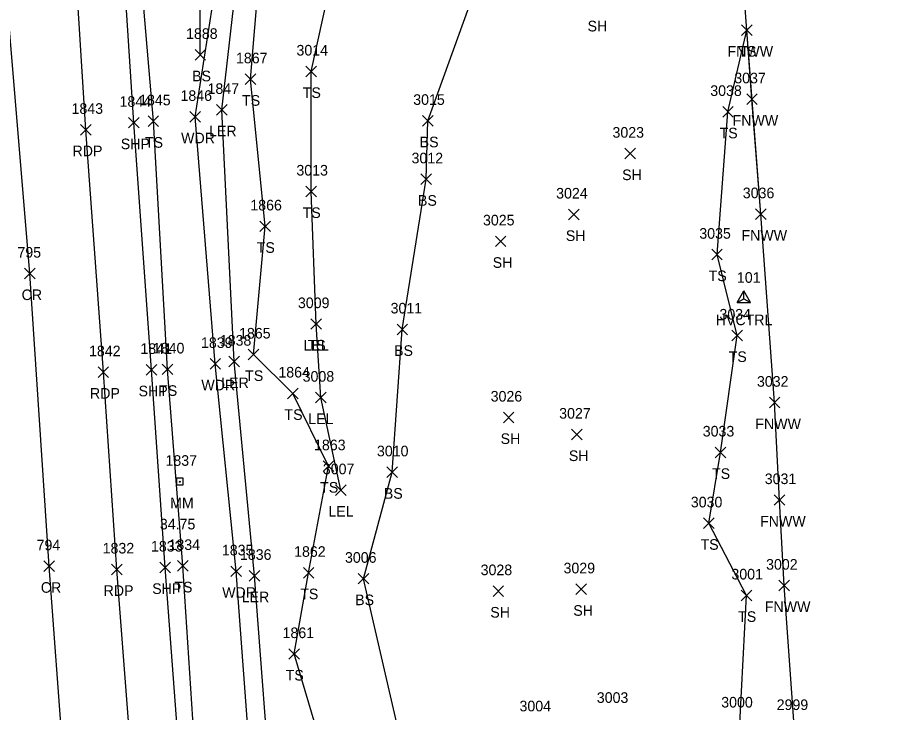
# Model space of a CAD drawing. Extents: x 1650221 to 1650634, y 244606 to 249996.
# Drawn here: x 1650455.2 to 1650620.5, y 244867.1 to 244998.2 of the extents above; entities that cross this region are included whole.
import ezdxf

# ---------------------------------------------------------------- set-up
doc = ezdxf.new("R2010")
doc.units = 0
for name, color, linetype in [('C_A', 7, 'Continuous'), ('C_I', 7, 'Continuous'), ('CPSM', 7, 'Continuous'), ('L_A', 7, 'Continuous'), ('L_I', 7, 'Continuous'), ('L_TIC', 7, 'Continuous'), ('LARO', 7, 'Continuous'), ('LAWA', 7, 'Continuous'), ('LELB', 7, 'Continuous'), ('LFNC', 7, 'Continuous'), ('LSOGP', 7, 'Continuous'), ('P_A', 7, 'Continuous'), ('P_I', 7, 'Continuous'), ('P_TIC', 7, 'Continuous'), ('PET', 7, 'Continuous'), ('PRC', 7, 'Continuous'), ('PSP', 7, 'Continuous'), ('S_A', 7, 'Continuous'), ('S_C', 7, 'Continuous'), ('S_I', 7, 'Continuous'), ('SRM', 7, 'Continuous')]:
    doc.layers.add(name, color=color, linetype=linetype)

msp = doc.modelspace()

# ---------------------------------------------------------------- linework, layer by layer
at = {"layer": 'CPSM'}
for p, q in [((1650591.02, 244944.49), (1650592.27, 244946.66)), ((1650593.52, 244944.49), (1650592.27, 244946.66)), ((1650592.27, 244945.21), (1650592.27, 244946.66)), ((1650591.02, 244944.49), (1650592.27, 244945.21)), ((1650591.02, 244944.49), (1650593.52, 244944.49)), ((1650592.27, 244945.21), (1650592.27, 244945.21)), ((1650592.27, 244945.21), (1650593.52, 244944.49))]:
    msp.add_line(p, q, dxfattribs=at)
at = {"layer": 'L_TIC'}
for points in [[(1650591.83, 244994.87), (1650593.83, 244996.87)], [(1650593.83, 244994.87), (1650591.83, 244996.87)], [(1650591.83, 244994.87), (1650593.83, 244996.87)], [(1650593.83, 244994.87), (1650591.83, 244996.87)], [(1650488.71, 244990.22), (1650490.71, 244992.22)], [(1650490.71, 244990.22), (1650488.71, 244992.22)], [(1650509.63, 244987.08), (1650511.63, 244989.08)], [(1650511.63, 244987.08), (1650509.63, 244989.08)], [(1650498.18, 244985.61), (1650500.18, 244987.61)], [(1650500.18, 244985.61), (1650498.18, 244987.61)], [(1650592.81, 244981.84), (1650594.81, 244983.84)], [(1650594.81, 244981.84), (1650592.81, 244983.84)], [(1650492.78, 244979.84), (1650494.78, 244981.84)], [(1650494.78, 244979.84), (1650492.78, 244981.84)], [(1650487.72, 244978.52), (1650489.72, 244980.52)], [(1650489.72, 244978.52), (1650487.72, 244980.52)], [(1650588.28, 244979.46), (1650590.28, 244981.46)], [(1650590.28, 244979.46), (1650588.28, 244981.46)], [(1650479.85, 244977.69), (1650481.85, 244979.69)], [(1650481.85, 244977.69), (1650479.85, 244979.69)], [(1650531.66, 244977.77), (1650533.66, 244979.77)], [(1650533.66, 244977.77), (1650531.66, 244979.77)], [(1650569.82, 244971.58), (1650571.82, 244973.58)], [(1650571.82, 244971.58), (1650569.82, 244973.58)], [(1650531.34, 244966.74), (1650533.34, 244968.74)], [(1650533.34, 244966.74), (1650531.34, 244968.74)], [(1650509.61, 244964.44), (1650511.61, 244966.44)], [(1650511.61, 244964.44), (1650509.61, 244966.44)], [(1650559.19, 244960.1), (1650561.19, 244962.1)], [(1650561.19, 244960.1), (1650559.19, 244962.1)], [(1650594.48, 244960.16), (1650596.48, 244962.16)], [(1650596.48, 244960.16), (1650594.48, 244962.16)], [(1650500.94, 244957.86), (1650502.94, 244959.86)], [(1650502.94, 244957.86), (1650500.94, 244959.86)], [(1650545.39, 244955.03), (1650547.39, 244957.03)], [(1650547.39, 244955.03), (1650545.39, 244957.03)], [(1650586.21, 244952.52), (1650588.21, 244954.52)], [(1650588.21, 244952.52), (1650586.21, 244954.52)], [(1650510.55, 244939.43), (1650512.55, 244941.43)], [(1650512.55, 244939.43), (1650510.55, 244941.43)], [(1650510.55, 244939.43), (1650512.55, 244941.43)], [(1650512.55, 244939.43), (1650510.55, 244941.43)], [(1650526.83, 244938.42), (1650528.83, 244940.42)], [(1650528.83, 244938.42), (1650526.83, 244940.42)], [(1650590, 244937.27), (1650592, 244939.27)], [(1650592, 244937.27), (1650590, 244939.27)], [(1650498.76, 244933.69), (1650500.76, 244935.69)], [(1650500.76, 244933.69), (1650498.76, 244935.69)], [(1650491.54, 244931.91), (1650493.54, 244933.91)], [(1650493.54, 244931.91), (1650491.54, 244933.91)], [(1650495.08, 244932.34), (1650497.08, 244934.34)], [(1650497.08, 244932.34), (1650495.08, 244934.34)], [(1650482.54, 244930.88), (1650484.54, 244932.88)], [(1650484.54, 244930.88), (1650482.54, 244932.88)], [(1650506.18, 244926.34), (1650508.18, 244928.34)], [(1650508.18, 244926.34), (1650506.18, 244928.34)], [(1650511.44, 244925.55), (1650513.44, 244927.55)], [(1650513.44, 244925.55), (1650511.44, 244927.55)], [(1650597.09, 244924.6), (1650599.09, 244926.6)], [(1650599.09, 244924.6), (1650597.09, 244926.6)], [(1650546.89, 244921.8), (1650548.89, 244923.8)], [(1650548.89, 244921.8), (1650546.89, 244923.8)], [(1650559.76, 244918.58), (1650561.76, 244920.58)], [(1650561.76, 244918.58), (1650559.76, 244920.58)], [(1650586.86, 244915.21), (1650588.86, 244917.21)], [(1650588.86, 244915.21), (1650586.86, 244917.21)], [(1650512.91, 244912.62), (1650514.91, 244914.62)], [(1650514.91, 244912.62), (1650512.91, 244914.62)], [(1650524.9, 244911.47), (1650526.9, 244913.47)], [(1650526.9, 244911.47), (1650524.9, 244913.47)], [(1650515.24, 244908.09), (1650517.24, 244910.09)], [(1650517.24, 244908.09), (1650515.24, 244910.09)], [(1650598, 244906.23), (1650600, 244908.23)], [(1650600, 244906.23), (1650598, 244908.23)], [(1650584.69, 244901.84), (1650586.69, 244903.84)], [(1650586.69, 244901.84), (1650584.69, 244903.84)], [(1650485.4, 244893.8), (1650487.4, 244895.8)], [(1650487.4, 244893.8), (1650485.4, 244895.8)], [(1650495.47, 244892.78), (1650497.47, 244894.78)], [(1650497.47, 244892.78), (1650495.47, 244894.78)], [(1650509.15, 244892.51), (1650511.15, 244894.51)], [(1650511.15, 244892.51), (1650509.15, 244894.51)], [(1650498.94, 244891.94), (1650500.94, 244893.94)], [(1650500.94, 244891.94), (1650498.94, 244893.94)], [(1650519.49, 244891.39), (1650521.49, 244893.39)], [(1650521.49, 244891.39), (1650519.49, 244893.39)], [(1650544.95, 244889.05), (1650546.95, 244891.05)], [(1650546.95, 244889.05), (1650544.95, 244891.05)], [(1650560.6, 244889.39), (1650562.6, 244891.39)], [(1650562.6, 244889.39), (1650560.6, 244891.39)], [(1650598.88, 244890.09), (1650600.88, 244892.09)], [(1650600.88, 244890.09), (1650598.88, 244892.09)], [(1650591.78, 244888.24), (1650593.78, 244890.24)], [(1650593.78, 244888.24), (1650591.78, 244890.24)], [(1650506.41, 244877.18), (1650508.41, 244879.18)], [(1650508.41, 244877.18), (1650506.41, 244879.18)]]:
    msp.add_lwpolyline(points, dxfattribs=at)
at = {"layer": 'LARO'}
for points in [[(1650518.65, 244690.58), (1650512.53, 244717.67), (1650511.45, 244754.99), (1650506.03, 244803.57), (1650503.39, 244847.38), (1650499.94, 244892.94), (1650496.08, 244933.34), (1650493.78, 244980.84), (1650496.92, 245008.36), (1650497.83, 245048.46), (1650495.91, 245077.72), (1650494.78, 245118.42), (1650491, 245121.86), (1650493.61, 245139.73)], [(1650516.24, 244909.09), (1650512.44, 244926.55), (1650511.55, 244940.43)]]:
    msp.add_lwpolyline(points, dxfattribs=at)
at = {"layer": 'LAWA'}
msp.add_lwpolyline([(1650532.93, 244639.7), (1650524.86, 244673.45), (1650514.54, 244690.35), (1650510.25, 244717.67), (1650508.53, 244755.66), (1650503.06, 244803.5), (1650499.99, 244846.46), (1650496.47, 244893.78), (1650492.54, 244932.91), (1650488.72, 244979.52), (1650493.15, 245007.74), (1650492.82, 245049.31), (1650491.93, 245077.75), (1650491, 245121.86)], dxfattribs=at)
at = {"layer": 'LELB'}
for points in [[(1650489.71, 244991.22), (1650489.69, 245009.71), (1650486.09, 245047.64), (1650483.87, 245079.25), (1650480.92, 245116.18), (1650479.42, 245140.42), (1650476.29, 245187.3), (1650474, 245221.05), (1650469.02, 245258.31), (1650465.71, 245285.05), (1650462.26, 245315.54), (1650460.48, 245356.55), (1650462.16, 245378.82), (1650455.67, 245427.55), (1650451.48, 245462.76), (1650449.79, 245512.44), (1650449.11, 245548.12), (1650443.42, 245590.47), (1650442.32, 245632.05), (1650435.43, 245684.43)], [(1650513.46, 244857.93), (1650507.41, 244878.18), (1650510.15, 244893.51), (1650513.91, 244913.62), (1650507.18, 244927.34), (1650499.76, 244934.69), (1650501.94, 244958.86), (1650499.18, 244986.61), (1650501.64, 245015.91), (1650508.66, 245023.34), (1650515.42, 245032.57), (1650513.14, 245052.72), (1650508.84, 245071.21), (1650503.85, 245088.66), (1650500.59, 245101.87), (1650501.31, 245122.87), (1650504.95, 245130.46), (1650502.44, 245141.72)], [(1650505.23, 244636.62), (1650502.16, 244675.85), (1650500.4, 244713.01), (1650496.37, 244756.26), (1650493.25, 244801.26), (1650489.44, 244848.53), (1650486.4, 244894.8), (1650483.54, 244931.88), (1650480.85, 244978.69), (1650478.22, 245009.62), (1650475.38, 245046.82), (1650473.75, 245078.48), (1650471.05, 245115.28), (1650468.74, 245140.33)], [(1650558.39, 244731), (1650560.16, 244746.89), (1650556.87, 244759.84), (1650538.74, 244776.67), (1650535.72, 244806.75), (1650532.14, 244826.66), (1650527.65, 244861.29), (1650520.49, 244892.39), (1650525.9, 244912.47), (1650527.83, 244939.42), (1650532.34, 244967.74), (1650532.66, 244978.77), (1650542.3, 245005.6), (1650546.24, 245022.45), (1650561.01, 245015.02), (1650576.46, 245035.33), (1650588.27, 245060.15)], [(1650511.55, 244940.43), (1650510.61, 244965.44), (1650510.63, 244988.08), (1650519.69, 245029.12)], [(1650592.09, 244640.67), (1650590.08, 244664.34), (1650598.12, 244676.67), (1650608.37, 244695.03), (1650608.68, 244719.58), (1650604.17, 244739.69), (1650600.42, 244769.47), (1650598.54, 244793.72), (1650597.34, 244816.58), (1650592.05, 244838.58), (1650591.52, 244865.08), (1650592.78, 244889.24), (1650585.69, 244902.84), (1650587.86, 244916.21), (1650591, 244938.27), (1650587.21, 244953.52), (1650589.28, 244980.46), (1650592.83, 244995.87)]]:
    msp.add_lwpolyline(points, dxfattribs=at)
at = {"layer": 'LFNC'}
msp.add_lwpolyline([(1650620.51, 244617.69), (1650617.31, 244662.42), (1650615.31, 244691.34), (1650613.19, 244720.04), (1650611.29, 244742.22), (1650608.76, 244769.54), (1650606.56, 244796.09), (1650605.06, 244817.05), (1650603.34, 244839.66), (1650601.74, 244864.61), (1650599.88, 244891.09), (1650599, 244907.23), (1650598.09, 244925.6), (1650595.48, 244961.16), (1650593.81, 244982.84), (1650592.83, 244995.87), (1650591.08, 245019.11), (1650589.36, 245042.09), (1650588.27, 245060.15), (1650586.18, 245090.82), (1650584.33, 245116.87), (1650580.12, 245176.92)], dxfattribs=at)
at = {"layer": 'LSOGP'}
msp.add_lwpolyline([(1650601.74, 244864.61), (1650599.88, 244891.09), (1650599, 244907.23), (1650598.09, 244925.6), (1650595.48, 244961.16), (1650592.83, 244995.87), (1650591.08, 245019.11), (1650589.36, 245042.09), (1650588.27, 245060.15), (1650586.18, 245090.82), (1650584.33, 245116.87), (1650579.44, 245186.98)], dxfattribs=at)
at = {"layer": 'P_TIC'}
for points in [[(1650476.17, 244977.41), (1650478.17, 244979.41)], [(1650478.17, 244977.41), (1650476.17, 244979.41)], [(1650467.1, 244976.08), (1650469.1, 244978.08)], [(1650469.1, 244976.08), (1650467.1, 244978.08)], [(1650456.56, 244948.95), (1650458.56, 244950.95)], [(1650458.56, 244948.95), (1650456.56, 244950.95)], [(1650470.41, 244930.35), (1650472.41, 244932.35)], [(1650472.41, 244930.35), (1650470.41, 244932.35)], [(1650479.52, 244930.79), (1650481.52, 244932.79)], [(1650481.52, 244930.79), (1650479.52, 244932.79)], [(1650460.18, 244893.73), (1650462.18, 244895.73)], [(1650462.18, 244893.73), (1650460.18, 244895.73)], [(1650472.97, 244893.14), (1650474.97, 244895.14)], [(1650474.97, 244893.14), (1650472.97, 244895.14)], [(1650482.1, 244893.51), (1650484.1, 244895.51)], [(1650484.1, 244893.51), (1650482.1, 244895.51)]]:
    msp.add_lwpolyline(points, dxfattribs=at)
at = {"layer": 'PET'}
msp.add_lwpolyline([(1650493.02, 244636.16), (1650490.06, 244675.27), (1650487.56, 244709.93), (1650484.05, 244756.69), (1650480.76, 244799.76), (1650477.49, 244848.34), (1650473.97, 244894.14), (1650471.41, 244931.35), (1650468.1, 244977.08), (1650466.09, 245009.13), (1650463.32, 245045.8), (1650460.91, 245077.88), (1650458.15, 245114.32), (1650456.62, 245139.84)], dxfattribs=at)
at = {"layer": 'PRC'}
msp.add_lwpolyline([(1650480.45, 244632.95), (1650477.62, 244672.59), (1650473.75, 244722.56), (1650470.31, 244766.82), (1650467.4, 244803.77), (1650467.33, 244807.38), (1650463.88, 244858.27), (1650461.18, 244894.73), (1650457.56, 244949.95), (1650452.93, 245005.14), (1650451.55, 245032.27), (1650447.57, 245085.81), (1650443.28, 245144.22)], dxfattribs=at)
at = {"layer": 'PSP'}
msp.add_lwpolyline([(1650502.02, 244636.4), (1650499, 244675.82), (1650496.5, 244711.9), (1650492.99, 244756.49), (1650489.99, 244801), (1650486.51, 244848.42), (1650483.1, 244894.51), (1650480.52, 244931.79), (1650477.17, 244978.41), (1650475.14, 245009.4), (1650472.27, 245046.65), (1650470.2, 245077.93), (1650467.35, 245115.19), (1650465.66, 245140.38)], dxfattribs=at)
at = {"layer": 'SRM'}
for p, q in [((1650486.48, 244911.34), (1650485.23, 244911.34)), ((1650485.23, 244911.34), (1650485.23, 244910.09)), ((1650486.48, 244911.34), (1650485.23, 244911.34)), ((1650485.23, 244911.34), (1650485.23, 244910.09)), ((1650486.48, 244910.09), (1650486.48, 244911.34)), ((1650486.48, 244910.09), (1650486.48, 244911.34)), ((1650485.23, 244910.09), (1650486.48, 244910.09)), ((1650485.23, 244910.09), (1650486.48, 244910.09))]:
    msp.add_line(p, q, dxfattribs=at)
msp.add_circle((1650485.83, 244910.68), 0.0833, dxfattribs=at)

# ---------------------------------------------------------------- texts
at = {"layer": 'C_A'}
msp.add_text('HVCTRL', height=2, dxfattribs=at).set_placement((1650586.97, 244940.21))
at = {"layer": 'C_I'}
msp.add_text('101', height=2, dxfattribs=at).set_placement((1650590.97, 244948.21))
at = {"layer": 'L_A'}
for s, p in [('SH', (1650562.79, 244995.63)), ('FNWW', (1650589.18, 244990.87)), ('TS', (1650591.24, 244990.87)), ('BS', (1650488.15, 244986.22)), ('TS', (1650497.59, 244981.61)), ('TS', (1650509.04, 244983.08)), ('FNWW', (1650590.15, 244977.84)), ('LER', (1650491.36, 244975.84)), ('TS', (1650587.69, 244975.46)), ('TS', (1650479.26, 244973.69)), ('WDR', (1650486.08, 244974.52)), ('BS', (1650531.1, 244973.77)), ('SH', (1650569.31, 244967.58)), ('BS', (1650530.78, 244962.74)), ('TS', (1650509.02, 244960.44)), ('SH', (1650558.68, 244956.1)), ('FNWW', (1650591.82, 244956.16)), ('TS', (1650500.35, 244953.86)), ('SH', (1650544.88, 244951.03)), ('TS', (1650585.62, 244948.52)), ('LEL', (1650509.19, 244935.43)), ('TS', (1650509.96, 244935.43)), ('BS', (1650526.27, 244934.42)), ('TS', (1650589.41, 244933.27)), ('TS', (1650498.17, 244929.69)), ('WDR', (1650489.9, 244927.91)), ('LER', (1650493.67, 244928.34)), ('TS', (1650481.94, 244926.88)), ('TS', (1650505.59, 244922.34)), ('LEL', (1650510.08, 244921.55)), ('FNWW', (1650594.44, 244920.6)), ('SH', (1650546.38, 244917.8)), ('SH', (1650559.25, 244914.58)), ('TS', (1650586.27, 244911.21)), ('TS', (1650512.32, 244908.62)), ('BS', (1650524.34, 244907.47)), ('LEL', (1650513.88, 244904.09)), ('FNWW', (1650595.34, 244902.23)), ('TS', (1650584.1, 244897.84)), ('TS', (1650484.81, 244889.8)), ('WDR', (1650493.84, 244888.78)), ('LER', (1650497.52, 244887.94)), ('TS', (1650508.56, 244888.51)), ('BS', (1650518.93, 244887.39)), ('FNWW', (1650596.23, 244886.09)), ('SH', (1650544.43, 244885.05)), ('SH', (1650560.09, 244885.39)), ('TS', (1650591.19, 244884.24)), ('TS', (1650505.82, 244873.18))]:
    msp.add_text(s, height=2, dxfattribs=at).set_placement(p)
at = {"layer": 'L_I'}
for s, p in [('1888', (1650487.02, 244994.22)), ('3014', (1650507.86, 244991.08)), ('1867', (1650496.44, 244989.61)), ('3037', (1650590.47, 244985.84)), ('1847', (1650491.08, 244983.84)), ('3038', (1650585.94, 244983.46)), ('1845', (1650478.16, 244981.69)), ('1846', (1650485.97, 244982.52)), ('3015', (1650529.89, 244981.77)), ('3023', (1650567.49, 244975.58)), ('3012', (1650529.57, 244970.74)), ('3013', (1650507.84, 244968.44)), ('3024', (1650556.86, 244964.1)), ('3036', (1650592.08, 244964.16)), ('1866', (1650499.15, 244961.86)), ('3025', (1650543.05, 244959.03)), ('3035', (1650583.87, 244956.52)), ('3009', (1650508.13, 244943.43)), ('3009', (1650508.13, 244943.43)), ('3011', (1650525.62, 244942.42)), ('3034', (1650587.67, 244941.27)), ('1865', (1650497.02, 244937.69)), ('1839', (1650489.84, 244935.91)), ('1838', (1650493.39, 244936.34)), ('1840', (1650480.76, 244934.88)), ('1864', (1650504.44, 244930.34)), ('3008', (1650509.02, 244929.55)), ('3032', (1650594.75, 244928.6)), ('3026', (1650544.5, 244925.8)), ('3027', (1650557.43, 244922.58)), ('3033', (1650584.52, 244919.21)), ('1863', (1650511.17, 244916.62)), ('3010', (1650523.04, 244915.47)), ('3007', (1650512.83, 244912.09)), ('3031', (1650596.22, 244910.23)), ('3030', (1650582.27, 244905.84)), ('1834', (1650483.71, 244897.8)), ('1835', (1650493.78, 244896.78)), ('1836', (1650497.19, 244895.94)), ('1862', (1650507.41, 244896.51)), ('3006', (1650517.01, 244895.39)), ('3002', (1650596.47, 244894.09)), ('3028', (1650542.61, 244893.05)), ('3029', (1650558.25, 244893.39)), ('3001', (1650589.93, 244892.24)), ('1861', (1650505.23, 244881.18)), ('3003', (1650564.53, 244868.96)), ('3000', (1650588.01, 244868.08)), ('2999', (1650598.47, 244867.61)), ('3004', (1650549.94, 244867.36))]:
    msp.add_text(s, height=2, dxfattribs=at).set_placement(p)
at = {"layer": 'P_A'}
for s, p in [('SHP', (1650474.7, 244973.41)), ('RDP', (1650465.59, 244972.08)), ('CR', (1650455.99, 244944.95)), ('RDP', (1650468.89, 244926.35)), ('SHP', (1650478.06, 244926.79)), ('CR', (1650459.61, 244889.73)), ('RDP', (1650471.46, 244889.14)), ('SHP', (1650480.63, 244889.51))]:
    msp.add_text(s, height=2, dxfattribs=at).set_placement(p)
at = {"layer": 'P_I'}
for s, p in [('1843', (1650465.41, 244980.08)), ('1844', (1650474.47, 244981.41)), ('795', (1650455.2, 244952.95)), ('1842', (1650468.71, 244934.35)), ('1841', (1650478.4, 244934.79)), ('794', (1650458.82, 244897.73)), ('1833', (1650480.4, 244897.51)), ('1832', (1650471.28, 244897.14))]:
    msp.add_text(s, height=2, dxfattribs=at).set_placement(p)
at = {"layer": 'S_A'}
msp.add_text('MM', height=2, dxfattribs=at).set_placement((1650484.02, 244905.68))
at = {"layer": 'S_C'}
msp.add_text('34.75', height=2, dxfattribs=at).set_placement((1650482.08, 244901.68))
at = {"layer": 'S_I'}
msp.add_text('1837', height=2, dxfattribs=at).set_placement((1650483.14, 244913.68))

doc.saveas('drawing.dxf')
